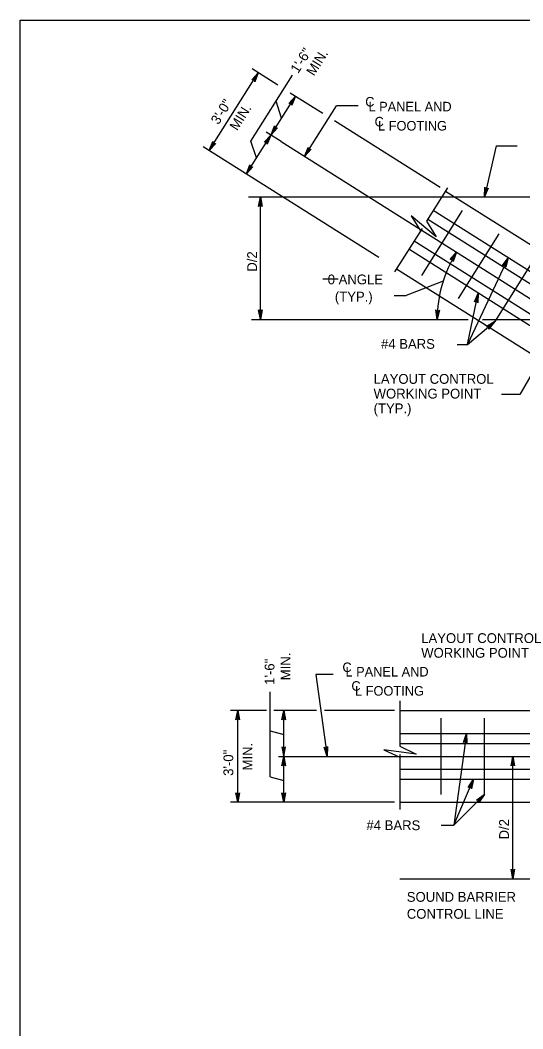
# Model space of a CAD drawing. Extents: x 3385 to 6532, y -616 to 1166.
# Drawn here: x 5483.3 to 5641, y -353.4 to -37.3 of the extents above; entities that cross this region are included whole.
import ezdxf

# ---------------------------------------------------------------- set-up
doc = ezdxf.new("R2010")
doc.units = 0
doc.layers.add('1', color=7, linetype='Continuous')
doc.layers.add('2', color=7, linetype='Continuous')

msp = doc.modelspace()

# ---------------------------------------------------------------- linework, layer by layer
at = {"layer": '1'}
for p, q in [((5564.2, -57.71), (5556.09, -52.59)), ((5542.67, -78.18), (5558.03, -53.81)), ((5555.73, -75.18), (5568.76, -54.51)), ((5554.3, -85.51), (5569.66, -61.15)), ((5565.36, -67.98), (5563.6, -62.7)), ((5578.24, -66.56), (5568.06, -60.14)), ((5572.55, -80), (5582.52, -64.19)), ((5589.4, -64.19), (5582.52, -64.19)), ((5615.04, -89.76), (5581.94, -68.89)), ((5565.2, -75.36), (5560.48, -72.38)), ((5557.47, -80.42), (5555.73, -75.18)), ((5565.2, -75.36), (5653.63, -131.12)), ((5595.81, -111.68), (5540.73, -76.96)), ((5632.63, -76.71), (5628.95, -92.72)), ((5632.63, -76.71), (5639.26, -76.71)), ((5617.39, -89.87), (5610.8, -100.32)), ((5616.77, -90.85), (5657.79, -116.72)), ((5554.94, -92.72), (5703.36, -92.72)), ((5558.68, -131.12), (5558.68, -92.72)), ((5622.01, -97), (5609.21, -117.3)), ((5655.71, -123.92), (5612.93, -96.94)), ((5611.22, -99.65), (5652.38, -125.6)), ((5609.39, -102.55), (5600.81, -116.16)), ((5633.51, -104.25), (5620.71, -124.55)), ((5606.95, -106.42), (5648.11, -132.37)), ((5651.55, -138.32), (5605.25, -109.12)), ((5636.46, -111.78), (5623.68, -138.93)), ((5645.01, -111.5), (5632.21, -131.8)), ((5601.41, -115.21), (5649.47, -145.52)), ((5583.12, -118.47), (5578.33, -118.47)), ((5615.99, -119.14), (5604.43, -123.56)), ((5623.68, -138.93), (5626.98, -122.82)), ((5600.62, -123.56), (5604.43, -123.56)), ((5555.9, -131.12), (5623.89, -131.12)), ((5623.68, -138.93), (5632.21, -131.8)), ((5628.32, -131.12), (5652.03, -131.12)), ((5652.83, -132.5), (5640.07, -154.59)), ((5620.44, -138.93), (5623.68, -138.93)), ((5640.07, -154.59), (5634.34, -154.59)), ((5581.48, -242.4), (5576.12, -242.4)), ((5576.12, -242.4), (5579.63, -268.03)), ((5561.75, -274.48), (5561.75, -247.78)), ((5602.42, -250.63), (5602.42, -264.82)), ((5560.58, -253.63), (5549.31, -253.63)), ((5551.6, -282.43), (5551.6, -253.63)), ((5576.3, -253.63), (5562.87, -253.63)), ((5566, -282.43), (5566, -253.63)), ((5600.76, -253.63), (5578.8, -253.63)), ((5602.42, -253.63), (5664.39, -253.63)), ((5615.37, -280.03), (5615.37, -256.03)), ((5628.94, -280.03), (5628.94, -256.03)), ((5561.75, -260), (5566, -261.17)), ((5602.42, -260.83), (5662.31, -260.83)), ((5623.34, -260.83), (5619.39, -289.64)), ((5602.42, -264.03), (5656.23, -264.03)), ((5564.37, -268.03), (5660.23, -268.03)), ((5602.42, -267.46), (5602.42, -284.69)), ((5637.87, -306.43), (5637.87, -268.03)), ((5561.75, -274.48), (5566, -275.65)), ((5602.42, -272.03), (5656.23, -272.03)), ((5602.42, -275.23), (5658.15, -275.23)), ((5619.39, -289.64), (5625.56, -275.23)), ((5619.39, -289.64), (5628.94, -280.03)), ((5600.76, -282.43), (5549.31, -282.43)), ((5602.42, -282.43), (5656.07, -282.43)), ((5615.42, -289.64), (5619.39, -289.64)), ((5602.42, -306.43), (5757.95, -306.43))]:
    msp.add_line(p, q, dxfattribs=at)
for points in [[(5558.03, -53.81), (5556.91, -56.64), (5556.9, -56.36), (5556.79, -56.15), (5556.64, -56.01), (5556.45, -55.94), (5556.22, -55.93), (5555.96, -56.04), (5558.03, -53.81), (5556.22, -55.93), (5556.45, -55.94), (5558.03, -53.81), (5556.64, -56.01), (5556.79, -56.15), (5558.03, -53.81), (5556.9, -56.36)], [(5569.66, -61.15), (5568.54, -63.97), (5568.53, -63.69), (5568.42, -63.49), (5568.27, -63.35), (5568.09, -63.27), (5567.85, -63.27), (5567.6, -63.38), (5569.66, -61.15), (5567.85, -63.27), (5568.09, -63.27), (5569.66, -61.15), (5568.27, -63.35), (5568.42, -63.49), (5569.66, -61.15), (5568.53, -63.69)], [(5562.04, -73.24), (5563.15, -70.42), (5563.17, -70.7), (5563.27, -70.91), (5563.42, -71.04), (5563.61, -71.12), (5563.84, -71.13), (5564.1, -71.02), (5562.04, -73.24), (5563.84, -71.13), (5563.61, -71.12), (5562.04, -73.24), (5563.42, -71.04), (5563.27, -70.91), (5562.04, -73.24), (5563.17, -70.7)], [(5542.67, -78.18), (5543.78, -75.36), (5543.79, -75.63), (5543.9, -75.84), (5544.05, -75.98), (5544.24, -76.06), (5544.47, -76.06), (5544.73, -75.95), (5542.67, -78.18), (5544.47, -76.06), (5544.24, -76.06), (5542.67, -78.18), (5544.05, -75.98), (5543.9, -75.84), (5542.67, -78.18), (5543.79, -75.63)], [(5561.96, -73.35), (5560.84, -76.17), (5560.83, -75.89), (5560.72, -75.68), (5560.57, -75.55), (5560.39, -75.47), (5560.15, -75.46), (5559.9, -75.57), (5561.96, -73.35), (5560.15, -75.46), (5560.39, -75.47), (5561.96, -73.35), (5560.57, -75.55), (5560.72, -75.68), (5561.96, -73.35), (5560.83, -75.89)], [(5572.55, -80), (5573.67, -77.18), (5573.68, -77.46), (5573.79, -77.66), (5573.94, -77.8), (5574.13, -77.88), (5574.36, -77.88), (5574.62, -77.77), (5572.55, -80), (5574.36, -77.88), (5574.13, -77.88), (5572.55, -80), (5573.94, -77.8), (5573.79, -77.66), (5572.55, -80), (5573.68, -77.46)], [(5554.3, -85.51), (5555.42, -82.69), (5555.43, -82.97), (5555.54, -83.18), (5555.69, -83.31), (5555.87, -83.39), (5556.11, -83.4), (5556.36, -83.29), (5554.3, -85.51), (5556.11, -83.4), (5555.87, -83.39), (5554.3, -85.51), (5555.69, -83.31), (5555.54, -83.18), (5554.3, -85.51), (5555.43, -82.97)], [(5628.95, -92.72), (5629.08, -89.69), (5629.18, -89.95), (5629.35, -90.11), (5629.54, -90.18), (5629.74, -90.19), (5629.96, -90.12), (5630.17, -89.94), (5628.95, -92.72), (5629.96, -90.12), (5629.74, -90.19), (5628.95, -92.72), (5629.54, -90.18), (5629.35, -90.11), (5628.95, -92.72), (5629.18, -89.95)], [(5558.68, -92.72), (5559.24, -95.7), (5559.08, -95.47), (5558.88, -95.35), (5558.68, -95.32), (5558.48, -95.35), (5558.28, -95.47), (5558.12, -95.7), (5558.68, -92.72), (5558.28, -95.47), (5558.48, -95.35), (5558.68, -92.72), (5558.68, -95.32), (5558.88, -95.35), (5558.68, -92.72), (5559.08, -95.47)], [(5610.8, -100.32), (5613.83, -105.23), (5605.98, -98.65), (5608.92, -103.29)], [(5620.21, -110.05), (5619.2, -112.91), (5619.17, -112.63), (5619.06, -112.42), (5618.91, -112.29), (5618.72, -112.22), (5618.48, -112.22), (5618.23, -112.34), (5620.21, -110.05), (5618.48, -112.22), (5618.72, -112.22), (5620.21, -110.05), (5618.91, -112.29), (5619.06, -112.42), (5620.21, -110.05), (5619.17, -112.63)], [(5636.46, -111.78), (5635.7, -114.72), (5635.67, -114.58), (5635.65, -114.44), (5635.58, -114.34), (5635.52, -114.25), (5635.44, -114.19), (5635.35, -114.13), (5635.26, -114.1), (5635.16, -114.08), (5635.04, -114.09), (5634.93, -114.1), (5634.8, -114.17), (5634.68, -114.24), (5636.46, -111.78), (5634.8, -114.17), (5634.93, -114.1), (5636.46, -111.78), (5635.04, -114.09), (5635.16, -114.08), (5636.46, -111.78), (5635.26, -114.1), (5635.35, -114.13), (5636.46, -111.78), (5635.44, -114.19), (5635.52, -114.25), (5636.46, -111.78), (5635.58, -114.34), (5635.65, -114.44), (5636.46, -111.78), (5635.67, -114.58)], [(5626.98, -122.82), (5626.93, -125.86), (5626.82, -125.6), (5626.65, -125.44), (5626.46, -125.37), (5626.25, -125.36), (5626.03, -125.44), (5625.83, -125.63), (5626.98, -122.82), (5626.03, -125.44), (5626.25, -125.36), (5626.98, -122.82), (5626.46, -125.37), (5626.65, -125.44), (5626.98, -122.82), (5626.82, -125.6)], [(5558.68, -131.12), (5558.12, -128.14), (5558.28, -128.37), (5558.48, -128.48), (5558.68, -128.52), (5558.88, -128.48), (5559.08, -128.37), (5559.24, -128.14), (5558.68, -131.12), (5559.08, -128.37), (5558.88, -128.48), (5558.68, -131.12), (5558.68, -128.52), (5558.48, -128.48), (5558.68, -131.12), (5558.28, -128.37)], [(5614.13, -131.12), (5613.73, -128.11), (5613.87, -128.35), (5614.07, -128.48), (5614.26, -128.52), (5614.46, -128.5), (5614.67, -128.39), (5614.84, -128.17), (5614.13, -131.12), (5614.67, -128.39), (5614.46, -128.5), (5614.13, -131.12), (5614.26, -128.52), (5614.07, -128.48), (5614.13, -131.12), (5613.87, -128.35)], [(5632.21, -131.8), (5630.29, -134.14), (5630.32, -134.01), (5630.36, -133.87), (5630.34, -133.76), (5630.32, -133.64), (5630.27, -133.56), (5630.22, -133.47), (5630.14, -133.4), (5630.07, -133.34), (5629.96, -133.3), (5629.85, -133.26), (5629.71, -133.27), (5629.57, -133.28), (5632.21, -131.8), (5629.71, -133.27), (5629.85, -133.26), (5632.21, -131.8), (5629.96, -133.3), (5630.07, -133.34), (5632.21, -131.8), (5630.14, -133.4), (5630.22, -133.47), (5632.21, -131.8), (5630.27, -133.56), (5630.32, -133.64), (5632.21, -131.8), (5630.34, -133.76), (5630.36, -133.87), (5632.21, -131.8), (5630.32, -134.01)], [(5551.6, -253.63), (5552.16, -256.61), (5552, -256.38), (5551.8, -256.26), (5551.6, -256.23), (5551.4, -256.26), (5551.2, -256.38), (5551.04, -256.61), (5551.6, -253.63), (5551.2, -256.38), (5551.4, -256.26), (5551.6, -253.63), (5551.6, -256.23), (5551.8, -256.26), (5551.6, -253.63), (5552, -256.38)], [(5566, -253.63), (5566.56, -256.61), (5566.4, -256.38), (5566.2, -256.26), (5566, -256.23), (5565.8, -256.26), (5565.6, -256.38), (5565.44, -256.61), (5566, -253.63), (5565.6, -256.38), (5565.8, -256.26), (5566, -253.63), (5566, -256.23), (5566.2, -256.26), (5566, -253.63), (5566.4, -256.38)], [(5623.34, -260.83), (5623.49, -263.86), (5623.36, -263.61), (5623.18, -263.46), (5622.99, -263.4), (5622.79, -263.41), (5622.57, -263.5), (5622.38, -263.71), (5623.34, -260.83), (5622.57, -263.5), (5622.79, -263.41), (5623.34, -260.83), (5622.99, -263.4), (5623.18, -263.46), (5623.34, -260.83), (5623.36, -263.61)], [(5566, -268.03), (5566.56, -265.04), (5566.4, -265.27), (5566.2, -265.39), (5566, -265.43), (5565.8, -265.39), (5565.6, -265.27), (5565.44, -265.04), (5566, -268.03), (5565.6, -265.27), (5565.8, -265.39), (5566, -268.03), (5566, -265.43), (5566.2, -265.39), (5566, -268.03), (5566.4, -265.27)], [(5579.63, -268.03), (5578.67, -265.15), (5578.86, -265.35), (5579.07, -265.44), (5579.27, -265.45), (5579.47, -265.39), (5579.65, -265.24), (5579.78, -265), (5579.63, -268.03), (5579.65, -265.24), (5579.47, -265.39), (5579.63, -268.03), (5579.27, -265.45), (5579.07, -265.44), (5579.63, -268.03), (5578.86, -265.35)], [(5602.42, -264.82), (5607.6, -267.36), (5597.45, -265.98), (5602.42, -268.34)], [(5566, -268.03), (5566.56, -271.01), (5566.4, -270.78), (5566.2, -270.66), (5566, -270.63), (5565.8, -270.66), (5565.6, -270.78), (5565.44, -271.01), (5566, -268.03), (5565.6, -270.78), (5565.8, -270.66), (5566, -268.03), (5566, -270.63), (5566.2, -270.66), (5566, -268.03), (5566.4, -270.78)], [(5637.87, -268.03), (5638.43, -271.01), (5638.27, -270.78), (5638.07, -270.66), (5637.87, -270.63), (5637.67, -270.66), (5637.47, -270.78), (5637.31, -271.01), (5637.87, -268.03), (5637.47, -270.78), (5637.67, -270.66), (5637.87, -268.03), (5637.87, -270.63), (5638.07, -270.66), (5637.87, -268.03), (5638.27, -270.78)], [(5625.56, -275.23), (5624.9, -278.19), (5624.87, -278.05), (5624.84, -277.91), (5624.77, -277.82), (5624.7, -277.73), (5624.62, -277.67), (5624.53, -277.62), (5624.43, -277.59), (5624.34, -277.57), (5624.22, -277.59), (5624.1, -277.6), (5623.99, -277.67), (5623.87, -277.75), (5625.56, -275.23), (5623.99, -277.67), (5624.1, -277.6), (5625.56, -275.23), (5624.22, -277.59), (5624.34, -277.57), (5625.56, -275.23), (5624.43, -277.59), (5624.53, -277.62), (5625.56, -275.23), (5624.62, -277.67), (5624.7, -277.73), (5625.56, -275.23), (5624.77, -277.82), (5624.84, -277.91), (5625.56, -275.23), (5624.87, -278.05)], [(5551.6, -282.43), (5551.04, -279.44), (5551.2, -279.67), (5551.4, -279.79), (5551.6, -279.83), (5551.8, -279.79), (5552, -279.67), (5552.16, -279.44), (5551.6, -282.43), (5552, -279.67), (5551.8, -279.79), (5551.6, -282.43), (5551.6, -279.83), (5551.4, -279.79), (5551.6, -282.43), (5551.2, -279.67)], [(5566, -282.43), (5565.44, -279.44), (5565.6, -279.67), (5565.8, -279.79), (5566, -279.83), (5566.2, -279.79), (5566.4, -279.67), (5566.56, -279.44), (5566, -282.43), (5566.4, -279.67), (5566.2, -279.79), (5566, -282.43), (5566, -279.83), (5565.8, -279.79), (5566, -282.43), (5565.6, -279.67)], [(5628.94, -280.03), (5627.23, -282.54), (5627.26, -282.4), (5627.28, -282.26), (5627.25, -282.15), (5627.22, -282.04), (5627.16, -281.95), (5627.1, -281.87), (5627.02, -281.81), (5626.94, -281.75), (5626.83, -281.73), (5626.71, -281.7), (5626.58, -281.72), (5626.44, -281.75), (5628.94, -280.03), (5626.58, -281.72), (5626.71, -281.7), (5628.94, -280.03), (5626.83, -281.73), (5626.94, -281.75), (5628.94, -280.03), (5627.02, -281.81), (5627.1, -281.87), (5628.94, -280.03), (5627.16, -281.95), (5627.22, -282.04), (5628.94, -280.03), (5627.25, -282.15), (5627.28, -282.26), (5628.94, -280.03), (5627.26, -282.4)], [(5637.87, -306.43), (5637.31, -303.44), (5637.47, -303.67), (5637.67, -303.79), (5637.87, -303.83), (5638.07, -303.79), (5638.27, -303.67), (5638.43, -303.44), (5637.87, -306.43), (5638.27, -303.67), (5638.07, -303.79), (5637.87, -306.43), (5637.87, -303.83), (5637.67, -303.79), (5637.87, -306.43), (5637.47, -303.67)]]:
    msp.add_lwpolyline(points, dxfattribs=at)
msp.add_arc((5653.63, -131.12), 39.51, 147.7689, 180, dxfattribs=at)
at = {"layer": '2'}
for p, q in [((5483.34, -601.31), (5483.34, -37.31)), ((5483.34, -37.31), (6269.34, -37.31))]:
    msp.add_line(p, q, dxfattribs=at)

# ---------------------------------------------------------------- texts
at = {"layer": '1'}
for s, rotation, p in [('1\'-6"', 57.769, (5570.52, -54.22)), ('MIN.', 57.769, (5575.49, -55)), ('3\'-0"', 57.769, (5545.53, -70.26)), ('MIN.', 57.769, (5551.42, -72.15)), ('D/2', 90, (5557.63, -116.14)), ('MIN.', 90, (5568.13, -244.19)), ('1\'-6"', 90, (5563.11, -245.62)), ('MIN.', 90, (5556.2, -272.46)), ('3\'-0"', 90, (5550.19, -274.15)), ('D/2', 90, (5636.65, -294.07))]:
    msp.add_text(s, height=3.072, rotation=rotation, dxfattribs=at).set_placement(p)
for s, height, p in [('C', 3, (5591.58, -64.38)), ('L PANEL AND', 3, (5592.6, -65.9)), ('C', 3, (5594.5, -70.62)), ('L FOOTING', 3, (5595.6, -71.9)), ('0 ANGLE', 3.072, (5579.81, -120.1)), ('(TYP.)', 3.072, (5582.05, -125.48)), ('#4 BARS', 3.072, (5596.53, -140.3)), ('LAYOUT CONTROL', 3.0721, (5594.21, -151.28)), ('WORKING POINT', 3.0721, (5594.21, -155.89)), ('(TYP.)', 3.072, (5594.21, -160.5)), ('LAYOUT CONTROL', 3.0721, (5609.14, -232.52)), ('WORKING POINT', 3.0721, (5609.14, -237.13)), ('C', 3, (5584.43, -241.63)), ('L PANEL AND', 3, (5585.38, -243.01)), ('C', 3, (5587.25, -247.48)), ('L FOOTING', 3, (5588.38, -249.01)), ('#4 BARS', 3.072, (5591.97, -291.17)), ('SOUND BARRIER', 3.0721, (5604.62, -313.62)), ('CONTROL LINE', 3.0721, (5604.62, -318.94))]:
    msp.add_text(s, height=height, dxfattribs=at).set_placement(p)

doc.saveas('drawing.dxf')
